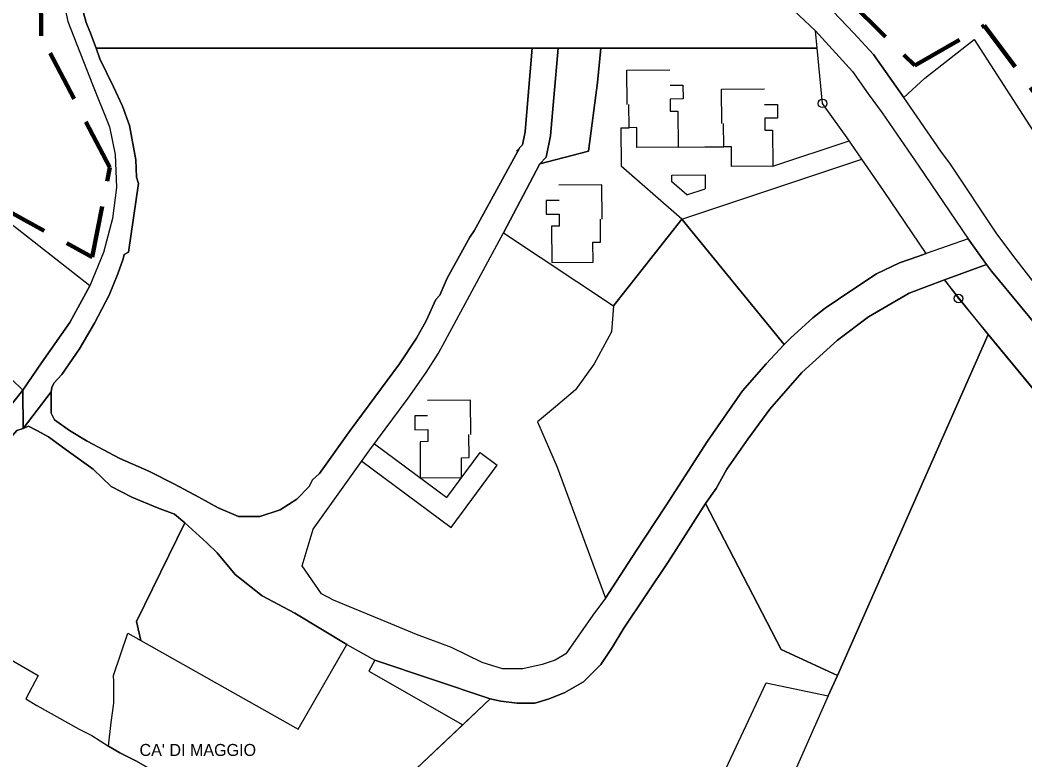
# Model space of a CAD drawing. Extents: x 654952 to 658955, y 890426 to 894481.
# Drawn here: x 657741.8 to 657975.8, y 892877.3 to 893049.5 of the extents above; entities that cross this region are included whole.
import ezdxf

# ---------------------------------------------------------------- set-up
doc = ezdxf.new("R2010")
doc.units = 0
doc.header["$LTSCALE"] = 4
doc.header["$PDMODE"] = 32
doc.header["$PDSIZE"] = 2
doc.linetypes.add('MEDIUM_DASHED', pattern=[4.5, 3, -1.5])
for name, color, linetype, lineweight in [('13', 7, 'Continuous', 25), ('18', 7, 'Continuous', 25), ('19', 7, 'Continuous', 25), ('20', 7, 'Continuous', 25), ('31', 7, 'Continuous', 25), ('35', 7, 'Continuous', 25), ('5', 7, 'Continuous', 25), ('6', 7, 'Continuous', 25), ('7', 7, 'MEDIUM_DASHED', 100), ('9', 7, 'Continuous', 25)]:
    doc.layers.add(name, color=color, linetype=linetype, lineweight=lineweight)
doc.layers.add('58', color=7, linetype='Continuous')

msp = doc.modelspace()

# ---------------------------------------------------------------- linework, layer by layer
at = {"layer": '13'}
for points in [[(657892.13, 892936.44), (657901.87, 892951.44), (657910, 892963.19), (657915.5, 892969.44), (657919.75, 892973.94), (657895.89, 893003.13), (657880, 892982.94)], [(657880, 892982.94), (657879.5, 892976.94), (657875.5, 892969.44), (657871.13, 892963.44), (657866.5, 892959.44), (657862.25, 892955.94), (657866.87, 892945.44), (657878.13, 892914.94)], [(657901.37, 892936.94), (657892.75, 892923.44), (657882.37, 892907.94), (657879.63, 892903.44), (657877, 892899.44)], [(657878.13, 892914.94), (657885.13, 892925.69), (657892.13, 892936.44)], [(657932.13, 892896.94), (657919, 892902.94), (657901.37, 892936.94)], [(657780.13, 892932.44), (657768.87, 892909.44), (657769.89, 892905.07), (657806.53, 892884.39), (657817.83, 892904.16)], [(657817.83, 892904.16), (657805.75, 892911.44), (657798.13, 892915.44), (657791.87, 892920.44), (657787.63, 892925.44), (657785.22, 892927.78), (657780.13, 892932.44)], [(657877, 892899.44), (657873, 892895.44), (657868.63, 892892.94), (657865, 892891.44), (657861.63, 892890.44), (657857.5, 892890.44), (657853.75, 892890.94), (657851.25, 892891.44), (657829.8, 892871.25)], [(657829.8, 892871.25), (657900.29, 892862.8), (657915.5, 892895.2), (657930.01, 892892.15), (657932.13, 892896.94)]]:
    msp.add_lwpolyline(points, dxfattribs=at)
at = {"layer": '18'}
for p, q in [((657937.83, 893017.12), (657934.39, 893022.09)), ((657862.81, 893015.99), (657874.13, 893018.94))]:
    msp.add_line(p, q, dxfattribs=at)
for points in [[(657928.67, 893030.1), (657927.42, 893042.94), (657927.02, 893047.01)], [(657927.02, 893047.01), (657935.66, 893037.55), (657939.33, 893032.34), (657942.56, 893027.86), (657951.13, 893015.44), (657962.57, 892998.57), (657952.82, 892995.13), (657942.88, 893009.8)], [(657867.06, 893042.94), (657866.1, 893031.43), (657865.32, 893022.56), (657864.29, 893017.6), (657862.81, 893015.99), (657874.13, 893018.94), (657862.81, 893015.99)], [(657874.13, 893018.94), (657876.25, 893034.94), (657877, 893042.94), (657867.06, 893042.94)], [(657934.39, 893022.09), (657931.19, 893026.53), (657928.67, 893030.1)], [(657994.29, 892959.11), (657989.25, 892965.44), (657968.05, 892991.04), (657966.89, 892992.59), (657957.1, 892988.98), (657960.05, 892985.04), (657960.35, 892984.66)], [(657960.35, 892984.66), (657981.49, 892959.14), (657983.75, 892956.29), (657994.29, 892959.11)]]:
    msp.add_lwpolyline(points, dxfattribs=at)
msp.add_lwpolyline([(657851.28, 892891.47), (657824.38, 892900.44), (657823, 892897.94), (657844.88, 892885.44)], close=True, dxfattribs=at)
for p in [(657928.67, 893030.1), (657960.35, 892984.66)]:
    msp.add_point(p, dxfattribs=at)
at = {"layer": '19'}
for points in [[(657768.62, 893105.66), (657763, 893097.44), (657761, 893093.44), (657759.13, 893089.94), (657757.75, 893085.94), (657757, 893083.44), (657756.25, 893078.94), (657755.75, 893071.94), (657755.63, 893065.94), (657755.63, 893059.94), (657755.5, 893057.94), (657755.5, 893055.94), (657755.88, 893053.44), (657756.5, 893051.19), (657757.13, 893048.94), (657758.13, 893046.44), (657759.48, 893042.94), (657927.42, 893042.94), (657927.02, 893047.01), (657915.59, 893057.77)], [(657762.37, 892880.44), (657763, 892885.94), (657763.63, 892890.44), (657763.63, 892895.44), (657763.5, 892896.94), (657766.88, 892906.77)], [(657766.88, 892906.77), (657806.53, 892884.39), (657817.83, 892904.16), (657824.38, 892900.44), (657823, 892897.94), (657844.88, 892885.44), (657829.8, 892871.25), (657900.29, 892862.8), (657915.5, 892895.2), (657930.01, 892892.15), (657906.64, 892839.36), (657892.37, 892845.94), (657880.87, 892821.44), (657877.63, 892816.44), (657821.13, 892847.44)], [(657821.13, 892847.44), (657795.13, 892861.94), (657768.87, 892876.94), (657765, 892878.94), (657762.37, 892880.44)]]:
    msp.add_lwpolyline(points, dxfattribs=at)
at = {"layer": '20'}
msp.add_lwpolyline([(658024.17, 892920.51), (658017.25, 892929.44), (658008, 892941.44), (657998, 892954.44), (657994.29, 892959.11), (657983.75, 892956.29), (657967.25, 892976.32), (657932.13, 892896.94), (657930.01, 892892.15), (657906.64, 892839.36), (657926, 892830.44), (657930.13, 892846.94), (657960.5, 892838.94), (657961.09, 892814.26), (657961.21, 892809.33)], dxfattribs=at)
at = {"layer": '31'}
for points in [[(657749.02, 893092.12), (657753.01, 893088.7), (657750.86, 893070.62), (657750.6, 893062.66), (657751.53, 893055.36), (657752.89, 893049.18), (657758.65, 893034.52), (657762.55, 893024.6), (657763.91, 893018.16), (657764.24, 893010.53), (657763.29, 893003.28), (657761.19, 892995.37), (657758, 892987.59), (657738.18, 893003.15)], [(657927.87, 893054.94), (657935.94, 893046.44), (657940.5, 893041.44), (657947.63, 893031.44), (657952.5, 893035.94), (657964, 893044.94), (657978.35, 893022.67)]]:
    msp.add_lwpolyline(points, dxfattribs=at)
at = {"layer": '35'}
msp.add_lwpolyline([(657738.53, 892958.42), (657742.4, 892963.34), (657736.85, 892968.59), (657725.84, 892979.61), (657703.8, 893002.77), (657689.48, 893017.1), (657678.82, 893022.62), (657667.07, 893025.92), (657655.32, 893027.76), (657647.25, 893025.93), (657631.09, 893017.11), (657618.6, 893011.96)], dxfattribs=at)
at = {"layer": '5'}
for p in [(657742.4, 892963.34), (657749, 892962.94)]:
    msp.add_line(p, (657742.5, 892954.44), dxfattribs=at)
for points in [[(657856.37, 893071.94), (657861.37, 893070.94), (657868.13, 893070.94), (657877.75, 893071.44), (657882.75, 893070.94), (657888.75, 893069.44), (657894.87, 893067.44), (657899.63, 893065.94), (657907.25, 893062.44), (657913, 893059.44), (657915.59, 893057.77), (657927.02, 893047.01)], [(657981, 892984.44), (657973.25, 892994.44), (657969.13, 892999.94), (657958.5, 893015.94), (657956.25, 893018.94), (657947.63, 893031.44), (657940.5, 893041.44), (657935.94, 893046.44), (657927.87, 893054.94)], [(657927.02, 893047.01), (657935.66, 893037.55), (657939.33, 893032.34), (657942.56, 893027.86), (657951.13, 893015.44), (657962.57, 892998.57), (657966.89, 892992.59), (657968.05, 892991.04)], [(657861.04, 893042.94), (657860.13, 893031.94), (657859.37, 893023.44), (657858.75, 893020.44), (657857.37, 893018.94), (657858.06, 893019.69), (657847.5, 893000.44), (657846.5, 892998.94), (657841.25, 892989.44), (657839.5, 892985.44), (657838.63, 892984.44), (657836.37, 892979.44), (657834.13, 892975.44), (657830.13, 892969.44), (657818.63, 892953.94), (657811.5, 892943.94), (657809.87, 892942.44), (657809.13, 892940.94)], [(657862.81, 893015.99), (657864.29, 893017.6), (657865.32, 893022.56), (657866.1, 893031.43), (657867.06, 893042.94), (657861.04, 893042.94)], [(657823.25, 892949.44), (657832.13, 892961.44), (657836.37, 892967.44), (657839.25, 892971.94), (657854.37, 892999.94), (657862.81, 893015.99)], [(657903.87, 892940.44), (657906.37, 892944.94), (657911.25, 892951.94), (657916.37, 892958.94), (657923.87, 892967.44), (657932.13, 892974.94), (657939.37, 892980.44), (657948.87, 892985.94), (657957.1, 892988.98), (657966.89, 892992.59), (657962.57, 892998.57), (657952.82, 892995.13)], [(657952.82, 892995.13), (657950.87, 892994.44), (657946.63, 892992.94), (657941.25, 892990.44), (657935.25, 892986.44), (657929.25, 892982.44), (657926.44, 892980.19), (657921.19, 892975.44), (657919.75, 892973.94)], [(657968.05, 892991.04), (657989.25, 892965.44), (657994.29, 892959.11)], [(657919.75, 892973.94), (657915.5, 892969.44), (657910, 892963.19), (657901.87, 892951.44), (657892.13, 892936.44)], [(657724.37, 892934.44), (657727.5, 892938.44), (657735.25, 892947.44), (657741, 892953.94), (657742.5, 892954.44), (657742.4, 892963.34), (657738.53, 892958.42), (657726.29, 892945.65), (657718.34, 892935.28), (657713.94, 892928.26), (657707.58, 892913.6), (657703.34, 892902.8), (657698.91, 892879.86), (657698.14, 892870.21)], [(657809.13, 892940.94), (657806.25, 892937.94), (657802.37, 892935.44), (657797.63, 892933.94), (657792.63, 892933.94), (657787.87, 892935.94), (657783.37, 892938.44), (657777.75, 892941.44), (657771.75, 892944.44), (657765, 892947.44), (657757.37, 892951.44), (657753.25, 892953.94), (657749.75, 892956.44), (657749, 892957.94), (657749, 892962.94), (657742.5, 892954.44)], [(657742.5, 892954.44), (657743.75, 892954.94), (657745.63, 892953.94), (657748.37, 892952.44), (657752.5, 892949.44), (657758.75, 892944.94), (657763, 892940.94), (657767.75, 892938.44), (657773.75, 892935.94), (657777.75, 892934.44), (657780.13, 892932.44), (657785.22, 892927.78)], [(657814.75, 892914.44), (657812, 892915.94), (657807.5, 892922.44), (657810, 892930.94), (657823.25, 892949.44)], [(657879.63, 892903.44), (657882.37, 892907.94), (657892.75, 892923.44), (657901.37, 892936.94), (657903.87, 892940.44)], [(657892.13, 892936.44), (657885.13, 892925.69), (657878.13, 892914.94), (657875.13, 892910.94), (657868.87, 892901.94), (657866.38, 892900.44)], [(657785.22, 892927.78), (657787.63, 892925.44), (657791.87, 892920.44), (657798.13, 892915.44)], [(657798.13, 892915.44), (657805.75, 892911.44), (657817.83, 892904.16), (657824.38, 892900.44), (657851.26, 892891.47)], [(657866.38, 892900.44), (657863.37, 892899.44), (657858.87, 892898.44), (657854.13, 892898.44), (657849.37, 892899.94), (657842.25, 892903.44), (657834.13, 892906.44), (657829.42, 892908.38), (657814.75, 892914.44)], [(657851.25, 892891.44), (657853.75, 892890.94), (657857.5, 892890.44), (657861.63, 892890.44), (657865, 892891.44), (657868.63, 892892.94), (657873, 892895.44), (657877, 892899.44), (657879.63, 892903.44)]]:
    msp.add_lwpolyline(points, dxfattribs=at)
at = {"layer": '6'}
for p, q in [((657881.72, 893024.42), (657883.62, 893024.43)), ((657881.72, 893024.42), (657881.78, 893015.48)), ((657917.08, 893015.47), (657934.87, 893021.4)), ((657895.89, 893003.13), (657881.78, 893015.48)), ((657895.89, 893003.13), (657937.82, 893017.11)), ((657897.03, 893008.78), (657893.56, 893011.82)), ((657897.03, 893008.78), (657901.32, 893010.21)), ((657895.89, 893003.13), (657880, 892982.94)), ((657824.29, 892950.85), (657841.16, 892938.37)), ((657841.16, 892938.37), (657848.89, 892948.82)), ((657848.89, 892948.82), (657852.91, 892945.85)), ((657821.32, 892946.83), (657842.2, 892931.38)), ((657842.2, 892931.38), (657852.91, 892945.85))]:
    msp.add_line(p, q, dxfattribs=at)
for points in [[(657883.18, 893029.83), (657883.12, 893037.83), (657893.12, 893037.9)], [(657893.15, 893034.3), (657896.15, 893034.32), (657896.17, 893031.12), (657893.17, 893031.1), (657893.19, 893028.3), (657894.99, 893028.31), (657895.05, 893019.91)], [(657905.21, 893025.38), (657905.16, 893033.38), (657915.15, 893033.45)], [(657895.05, 893019.91), (657885.45, 893019.85), (657885.42, 893024.45), (657883.62, 893024.43), (657883.58, 893029.83)], [(657915.18, 893029.85), (657918.18, 893029.87), (657918.2, 893026.67), (657915.2, 893026.65), (657915.22, 893023.85), (657917.02, 893023.87), (657917.08, 893015.47)], [(657917.08, 893015.47), (657907.48, 893015.4), (657907.45, 893020), (657905.65, 893019.99), (657905.61, 893025.39)], [(657895.05, 893019.91), (657901.25, 893019.96), (657905.65, 893019.99)], [(657893.56, 893011.82), (657893.55, 893013.42), (657901.29, 893013.47), (657901.32, 893010.21)], [(657877.34, 893003.16), (657877.28, 893011.16), (657867.28, 893011.09)], [(657867.31, 893007.49), (657864.31, 893007.47), (657864.33, 893004.27), (657867.33, 893004.29), (657867.35, 893001.49), (657865.55, 893001.48), (657865.61, 892993.08)], [(657865.61, 892993.08), (657875.21, 892993.15), (657875.18, 892997.75), (657876.98, 892997.76), (657876.94, 893003.16)], [(657846.71, 892953.02), (657846.66, 892961.02), (657836.66, 892960.95)], [(657836.68, 892957.35), (657833.68, 892957.33), (657833.71, 892954.13), (657836.71, 892954.15), (657836.73, 892951.35), (657834.93, 892951.34), (657834.98, 892942.94)], [(657834.98, 892942.94), (657844.58, 892943.01), (657844.55, 892947.61), (657846.35, 892947.62), (657846.31, 892953.02)]]:
    msp.add_lwpolyline(points, dxfattribs=at)
at = {"layer": '7'}
msp.add_lwpolyline([(657691.52, 892856.93), (657700.1, 892905.18), (657716.04, 892939.12), (657738.11, 892964.47), (657720.54, 892980.83), (657736.88, 893006.17), (657758.54, 892994.31), (657762.63, 893015.17), (657746.69, 893045.84), (657746.28, 893098.18), (657793.69, 893168.1), (657894.63, 893200), (657931.41, 893195.5), (657935.09, 893168.92), (657902.81, 893157.06), (657895.04, 893112.9), (657880.84, 893081.86), (657922.01, 893066.69), (657950.13, 893038.88), (657966.34, 893048.2), (657980.93, 893028.74)], dxfattribs=at)
at = {"layer": '9'}
for p, q in [((657937.83, 893017.12), (657934.39, 893022.09)), ((657962.57, 892998.57), (657966.89, 892992.59))]:
    msp.add_line(p, q, dxfattribs=at)
for points in [[(657749.02, 893092.12), (657753.01, 893088.7), (657750.86, 893070.62), (657750.6, 893062.66), (657751.53, 893055.36), (657752.89, 893049.18), (657758.65, 893034.52), (657762.55, 893024.6), (657763.91, 893018.16), (657764.24, 893010.53), (657763.29, 893003.28), (657761.19, 892995.37), (657758, 892987.59)], [(657769.37, 893011.44), (657768.87, 893012.94), (657768.75, 893016.94), (657767.25, 893024.94), (657765.63, 893029.44), (657763.5, 893033.94), (657760.37, 893040.44), (657759.48, 893042.94), (657758.13, 893046.44), (657757.13, 893048.94), (657756.5, 893051.19), (657755.88, 893053.44), (657755.5, 893055.94), (657755.5, 893057.94), (657755.63, 893059.94)], [(657981, 892984.44), (657973.25, 892994.44), (657969.13, 892999.94), (657958.5, 893015.94), (657956.25, 893018.94), (657947.63, 893031.44), (657952.5, 893035.94), (657964, 893044.94), (657978.35, 893022.67)], [(657857.37, 893018.94), (657858.75, 893020.44), (657859.37, 893023.44), (657860.13, 893031.94), (657861.04, 893042.94), (657759.48, 893042.94)], [(657759.48, 893042.94), (657760.37, 893040.44), (657763.5, 893033.94), (657765.63, 893029.44), (657767.25, 893024.94), (657768.75, 893016.94), (657768.87, 893012.94), (657769.37, 893011.44), (657767, 892995.44)], [(657877, 893042.94), (657876.25, 893034.94), (657874.13, 893018.94), (657862.81, 893015.99), (657854.37, 892999.94), (657880, 892982.94), (657895.89, 893003.13), (657919.75, 892973.94)], [(657934.39, 893022.09), (657931.19, 893026.53), (657928.67, 893030.1), (657927.42, 893042.94), (657877, 893042.94)], [(657749, 892957.94), (657749.75, 892956.44), (657753.25, 892953.94), (657757.37, 892951.44), (657765, 892947.44), (657771.75, 892944.44), (657777.75, 892941.44), (657783.37, 892938.44), (657787.87, 892935.94), (657792.63, 892933.94), (657797.63, 892933.94), (657802.37, 892935.44), (657806.25, 892937.94), (657809.13, 892940.94), (657809.87, 892942.44), (657811.5, 892943.94), (657818.63, 892953.94), (657830.13, 892969.44), (657834.13, 892975.44), (657836.37, 892979.44), (657838.63, 892984.44), (657839.5, 892985.44), (657841.25, 892989.44), (657846.5, 892998.94), (657847.5, 893000.44), (657858.06, 893019.69), (657857.37, 893018.94)], [(657919.75, 892973.94), (657921.19, 892975.44), (657926.44, 892980.19), (657929.25, 892982.44), (657935.25, 892986.44), (657941.25, 892990.44), (657946.63, 892992.94), (657950.87, 892994.44), (657952.82, 892995.13), (657942.88, 893009.8), (657937.83, 893017.12)], [(657751.5, 892966.94), (657755.63, 892972.94), (657759.13, 892978.94), (657762.5, 892985.44), (657764.5, 892990.44), (657765.75, 892993.94), (657766, 892994.94), (657767, 892995.44), (657769.37, 893011.44)], [(657823.25, 892949.44), (657832.13, 892961.44), (657836.37, 892967.44), (657839.25, 892971.94), (657854.37, 892999.94), (657880, 892982.94)], [(657767, 892995.44), (657766, 892994.94), (657765.75, 892993.94), (657764.5, 892990.44), (657762.5, 892985.44), (657759.13, 892978.94), (657755.63, 892972.94), (657751.5, 892966.94), (657749.63, 892964.94), (657749.13, 892963.94), (657749, 892962.94), (657749, 892957.94)], [(657758, 892987.59), (657753.37, 892979.1), (657746.77, 892969.69), (657742.4, 892963.34), (657742.5, 892954.44), (657749, 892962.94)], [(657957.1, 892988.98), (657948.87, 892985.94), (657939.37, 892980.44), (657932.13, 892974.94), (657923.87, 892967.44), (657916.37, 892958.94), (657911.25, 892951.94), (657906.37, 892944.94), (657903.87, 892940.44), (657901.37, 892936.94)], [(657901.37, 892936.94), (657919, 892902.94), (657932.13, 892896.94), (657967.25, 892976.32), (657957.1, 892988.98)], [(657880, 892982.94), (657879.5, 892976.94), (657875.5, 892969.44), (657871.13, 892963.44), (657866.5, 892959.44), (657862.25, 892955.94)], [(657749, 892962.94), (657749.13, 892963.94), (657749.63, 892964.94), (657751.5, 892966.94)], [(657763, 892940.94), (657758.75, 892944.94), (657752.5, 892949.44), (657748.37, 892952.44), (657745.63, 892953.94), (657743.75, 892954.94), (657742.5, 892954.44), (657741, 892953.94), (657735.25, 892947.44), (657727.5, 892938.44), (657724.37, 892934.44)], [(657862.25, 892955.94), (657866.87, 892945.44), (657878.13, 892914.94), (657875.13, 892910.94), (657868.87, 892901.94), (657866.38, 892900.44)], [(657814.75, 892914.44), (657812, 892915.94), (657807.5, 892922.44), (657810, 892930.94), (657823.25, 892949.44)], [(657769.89, 892905.07), (657768.87, 892909.44), (657780.13, 892932.44), (657777.75, 892934.44), (657773.75, 892935.94), (657767.75, 892938.44), (657763, 892940.94)], [(657724.37, 892934.44), (657719.63, 892927.44), (657717.13, 892923.44), (657715.37, 892919.44), (657713.87, 892915.44), (657746, 892896.94), (657743.13, 892891.44), (657745.63, 892889.94), (657755.5, 892884.44), (657758.5, 892882.94), (657762.37, 892880.44)], [(657704.63, 892885.94), (657705.75, 892893.44), (657705.87, 892894.94), (657709.5, 892904.94), (657713.87, 892915.44), (657746, 892896.94), (657743.13, 892891.44), (657745.63, 892889.94)], [(657866.38, 892900.44), (657863.37, 892899.44), (657858.87, 892898.44), (657854.13, 892898.44), (657849.37, 892899.94), (657842.25, 892903.44), (657834.13, 892906.44), (657829.42, 892908.38), (657814.75, 892914.44)], [(657762.37, 892880.44), (657763, 892885.94), (657763.63, 892890.44), (657763.63, 892895.44), (657763.5, 892896.94), (657766.88, 892906.77), (657769.89, 892905.07)], [(657745.63, 892889.94), (657755.5, 892884.44), (657758.5, 892882.94), (657762.37, 892880.44), (657765, 892878.94)], [(657765, 892878.94), (657768.87, 892876.94), (657795.13, 892861.94), (657821.13, 892847.44), (657807.37, 892821.44), (657805, 892822.44), (657801.37, 892824.94), (657790.87, 892830.44), (657786.25, 892832.94), (657775.37, 892839.44), (657771.13, 892841.44), (657754.63, 892850.44), (657749.13, 892852.94)]]:
    msp.add_lwpolyline(points, dxfattribs=at)
msp.add_lwpolyline([(657758, 892987.59), (657738.18, 893003.15), (657732.92, 892995.41), (657728.92, 892988.4), (657724.57, 892980.94), (657736.85, 892968.59), (657742.4, 892963.34), (657746.77, 892969.69), (657753.37, 892979.1)], close=True, dxfattribs=at)

# ---------------------------------------------------------------- texts
at = {"layer": '58'}
msp.add_text("CA' DI MAGGIO", height=2.801, dxfattribs=at).set_placement((657769.58, 892878.17))

doc.saveas('drawing.dxf')
